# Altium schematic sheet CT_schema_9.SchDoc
size 281 x 153 mm
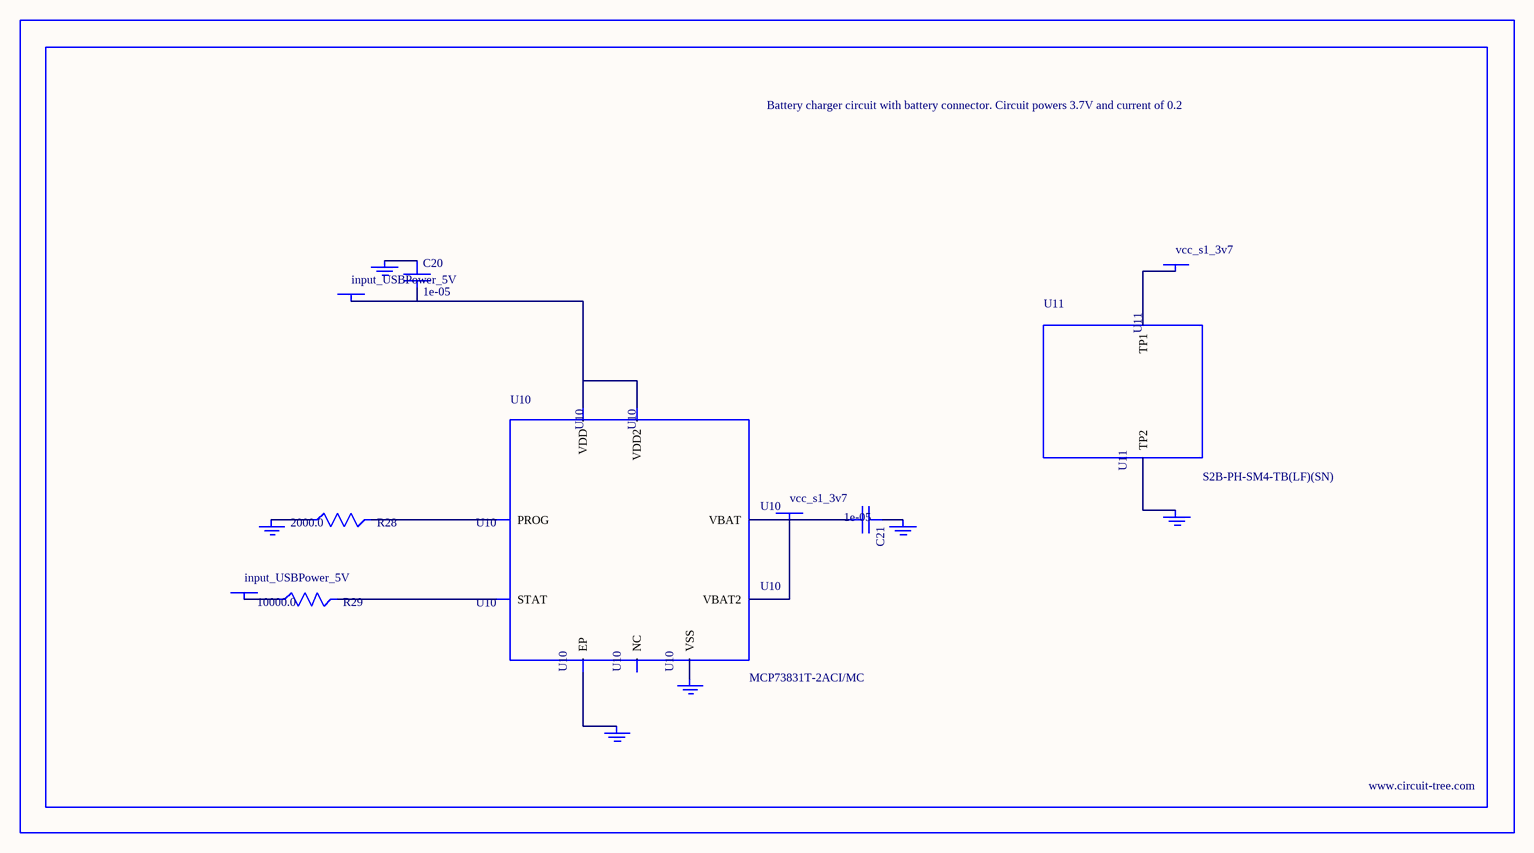
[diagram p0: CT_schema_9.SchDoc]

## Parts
BORDER8  (no value)
C20  1e-05  [C1206]
C21  1e-05  [C1206]
GND_INSTANCE_8_0  (no value)
GND_INSTANCE_8_1  (no value)
GND_INSTANCE_8_2  (no value)
GND_INSTANCE_8_3  (no value)
GND_INSTANCE_8_4  (no value)
GND_INSTANCE_8_5  (no value)
POWER_INSTANCE_8_0  input_USBPower_5V
POWER_INSTANCE_8_1  input_USBPower_5V
POWER_INSTANCE_8_2  vcc_s1_3v7
POWER_INSTANCE_8_3  vcc_s1_3v7
R28  2000.0  [R0603]
R29  10000.0  [R0603]
U10  MCP73831T-2ACI/MC  [DFN8_2X3MC]
U11  S2B-PH-SM4-TB(LF)(SN)  [JST-2-SMD]

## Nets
NetC20_1: C20.1 GND_INSTANCE_8_0.0(GND)
NetC20_2: C20.2 POWER_INSTANCE_8_0.0(PWR) U10.1(VDD) U10.2(VDD2)
NetC21_1: C21.1 GND_INSTANCE_8_1.0(GND)
NetC21_2: C21.2 POWER_INSTANCE_8_2.0(PWR) U10.3(VBAT) U10.4(VBAT2)
NetGND_INSTANCE_8_2_0: GND_INSTANCE_8_2.0(GND) R28.1
NetGND_INSTANCE_8_3_0: GND_INSTANCE_8_3.0(GND) U10.9(EP)
NetGND_INSTANCE_8_4_0: GND_INSTANCE_8_4.0(GND) U10.6(VSS)
NetGND_INSTANCE_8_5_0: GND_INSTANCE_8_5.0(GND) U11.2(TP2)
NetPOWER_INSTANCE_8_1_0: POWER_INSTANCE_8_1.0(PWR) R29.1
NetPOWER_INSTANCE_8_3_0: POWER_INSTANCE_8_3.0(PWR) U11.1(TP1)
NetR28_2: R28.2 U10.8(PROG)
NetR29_2: R29.2 U10.5(STAT)

Not connected (* = marked no-connect by the designer): U10 7(NC)

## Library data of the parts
BORDER8 = BORDER_PAGE8
C20 C21 = C1206C106K3RACTU
GND_INSTANCE_8_0-GND_INSTANCE_8_5 = GND
POWER_INSTANCE_8_0-POWER_INSTANCE_8_3 = PWR
R28 = RC0603JR-072KL
R29 = RC0603JR-0710KL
